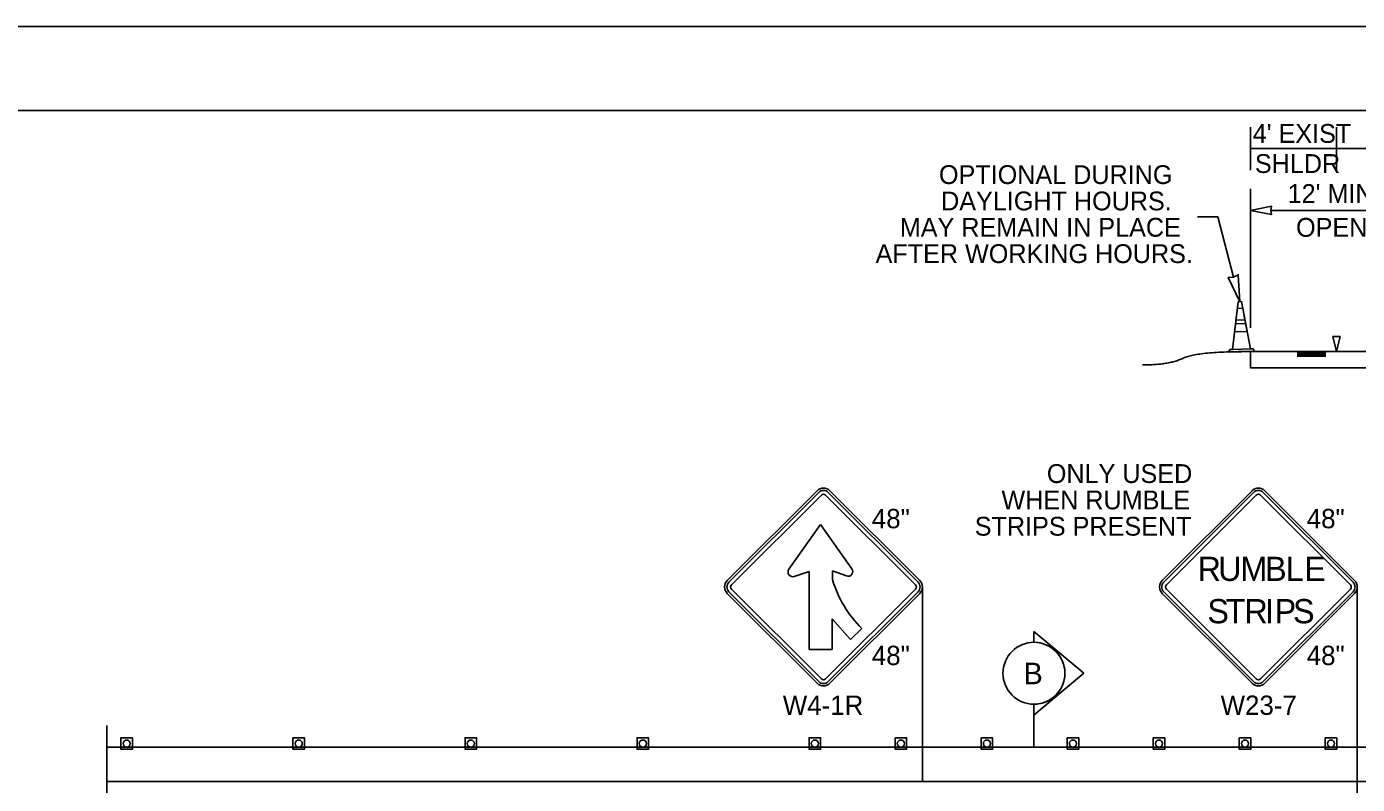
# Model space of a CAD drawing. Extents: x 99999 to 100116, y 99995 to 100013.
# Drawn here: x 100067.897 to 100072.847, y 100007.868 to 100010.687 of the extents above; entities that cross this region are included whole.
import ezdxf

# ---------------------------------------------------------------- set-up
doc = ezdxf.new("R2010")
doc.units = 0
for name, color, linetype in [('RD_MK_LineEdgeYellow', 7, 'Continuous'), ('SH_GI_PlotLimits', 7, 'Continuous'), ('SH_GI_SectionCut', 7, 'Continuous'), ('SH_GI_SheetBorder', 7, 'Continuous'), ('SH_TI_WZSectionCut', 7, 'Continuous'), ('TR_SN_ConstructionSigns', 7, 'Continuous'), ('TR_WZ_TrafficCone', 7, 'Continuous'), ('TR_WZ_TrafficConeElev', 7, 'Continuous'), ('TR_WZ_WorkZoneDetails', 7, 'Continuous'), ('TR_WZ_WorkZoneTextCurrent', 7, 'Continuous')]:
    doc.layers.add(name, color=color, linetype=linetype)

msp = doc.modelspace()

# ---------------------------------------------------------------- linework, layer by layer
at = {"layer": 'RD_MK_LineEdgeYellow'}
msp.add_line((100068.195, 100007.8789), (100075.43, 100007.8789), dxfattribs=at)
at = {"layer": 'SH_GI_PlotLimits'}
msp.add_lwpolyline([(100059.0625, 99999.6875), (100076.0625, 99999.6875), (100076.0625, 100010.6875), (100059.0625, 100010.6875)], close=True, dxfattribs=at)
at = {"layer": 'SH_GI_SectionCut'}
for p, q in [((100071.6444, 100008.397), (100071.6444, 100008.4377)), ((100071.6444, 100008.4377), (100071.8305, 100008.2818)), ((100071.8305, 100008.2818), (100071.6444, 100008.1259)), ((100071.6444, 100008.1259), (100071.6444, 100008.1666)), ((100071.6444, 100008.1259), (100071.6444, 100008.0069))]:
    msp.add_line(p, q, dxfattribs=at)
msp.add_circle((100071.6444, 100008.2818), 0.1152, dxfattribs=at)
msp.add_circle((100071.6444, 100008.2818), 0.1152, dxfattribs=at)
for start, end in [(90.0016, 269.9972), (269.9972, 90.0016), (269.9972, 90.0016)]:
    msp.add_arc((100071.6444, 100008.2818), 0.1152, start, end, dxfattribs=at)
at = {"layer": 'SH_GI_SheetBorder'}
msp.add_line((100060, 100010.375), (100075.75, 100010.375), dxfattribs=at)
at = {"layer": 'SH_TI_WZSectionCut'}
for p, q in [((100072.45, 100009.5666), (100072.45, 100010.0836)), ((100072.525, 100010.0036), (100073.335, 100010.0036))]:
    msp.add_line(p, q, dxfattribs=at)
msp.add_lwpolyline([(100072.45, 100010.0036), (100072.5286, 100009.9882), (100072.525, 100010.0036), (100072.5286, 100010.019)], close=True, dxfattribs=at)
at = {"layer": 'TR_SN_ConstructionSigns'}
for p, q in [((100070.8376, 100008.9607), (100070.5035, 100008.6266)), ((100070.8436, 100008.9548), (100070.5095, 100008.6207)), ((100071.2135, 100008.6207), (100070.8794, 100008.9548)), ((100071.2195, 100008.6266), (100070.8854, 100008.9607)), ((100072.4555, 100008.9607), (100072.1214, 100008.6266)), ((100072.4614, 100008.9548), (100072.1273, 100008.6207)), ((100072.8313, 100008.6207), (100072.4972, 100008.9548)), ((100072.8373, 100008.6266), (100072.5032, 100008.9607)), ((100070.5194, 100008.6107), (100070.8536, 100008.9448)), ((100070.8695, 100008.9448), (100071.2036, 100008.6107)), ((100072.1373, 100008.6107), (100072.4714, 100008.9448)), ((100072.4873, 100008.9448), (100072.8214, 100008.6107)), ((100070.7327, 100008.669), (100070.8506, 100008.8347)), ((100070.8506, 100008.8347), (100070.9671, 100008.6708)), ((100070.8079, 100008.6609), (100070.753, 100008.6419)), ((100070.8079, 100008.3708), (100070.8079, 100008.6609)), ((100070.9466, 100008.6438), (100070.8947, 100008.6624)), ((100070.8947, 100008.6624), (100070.8947, 100008.63)), ((100070.5035, 100008.5789), (100070.8376, 100008.2448)), ((100070.5095, 100008.5849), (100070.8436, 100008.2508)), ((100070.8536, 100008.2607), (100070.5194, 100008.5948)), ((100071.2036, 100008.5948), (100070.8695, 100008.2607)), ((100070.8794, 100008.2508), (100071.2135, 100008.5849)), ((100070.8854, 100008.2448), (100071.2195, 100008.5789)), ((100072.1214, 100008.5789), (100072.4555, 100008.2448)), ((100072.1273, 100008.5849), (100072.4614, 100008.2508)), ((100072.4714, 100008.2607), (100072.1373, 100008.5948)), ((100072.8214, 100008.5948), (100072.4873, 100008.2607)), ((100072.4972, 100008.2508), (100072.8313, 100008.5849)), ((100072.5032, 100008.2448), (100072.8373, 100008.5789)), ((100070.9624, 100008.4077), (100070.8932, 100008.4842)), ((100070.8932, 100008.4842), (100070.8932, 100008.3708)), ((100071.0036, 100008.4489), (100070.9624, 100008.4077)), ((100070.8932, 100008.3708), (100070.8079, 100008.3708))]:
    msp.add_line(p, q, dxfattribs=at)
for centre, radius, start, end in [((100070.8615, 100008.9369), 0.0338, 45, 135), ((100070.8615, 100008.9369), 0.0253, 45, 135), ((100070.8615, 100008.9369), 0.0113, 45, 135), ((100072.4793, 100008.9369), 0.0338, 45, 135), ((100072.4793, 100008.9369), 0.0253, 45, 135), ((100072.4793, 100008.9369), 0.0113, 45, 135), ((100070.7472, 100008.6587), 0.0177, 144.5862, 289.1062), ((100070.9526, 100008.6606), 0.0177, 250.3331, 35.4138), ((100070.5274, 100008.6028), 0.0338, 135, 225), ((100070.5274, 100008.6028), 0.0253, 135, 225), ((100070.5274, 100008.6028), 0.0113, 135, 225), ((100071.3078, 100008.7551), 0.4316, 196.843, 225.185), ((100071.1956, 100008.6028), 0.0113, 315, 45), ((100071.1956, 100008.6028), 0.0253, 315, 45), ((100071.1956, 100008.6028), 0.0338, 315, 45), ((100072.1452, 100008.6028), 0.0338, 135, 225), ((100072.1452, 100008.6028), 0.0253, 135, 225), ((100072.1452, 100008.6028), 0.0113, 135, 225), ((100072.8134, 100008.6028), 0.0113, 315, 45), ((100072.8134, 100008.6028), 0.0253, 315, 45), ((100072.8134, 100008.6028), 0.0338, 315, 45), ((100070.8615, 100008.2687), 0.0113, 225, 315), ((100072.4793, 100008.2687), 0.0113, 225, 315), ((100070.8615, 100008.2687), 0.0338, 225, 315), ((100070.8615, 100008.2687), 0.0253, 225, 315), ((100072.4793, 100008.2687), 0.0338, 225, 315), ((100072.4793, 100008.2687), 0.0253, 225, 315)]:
    msp.add_arc(centre, radius, start, end, dxfattribs=at)
at = {"layer": 'TR_WZ_TrafficCone'}
for points in [[(100068.2481, 100008.0416), (100068.2907, 100008.0416), (100068.2907, 100007.9989), (100068.2481, 100007.9989), (100068.2481, 100008.0416)], [(100068.2481, 100007.9989), (100068.2907, 100007.9989), (100068.2907, 100008.0416), (100068.2481, 100008.0416), (100068.2481, 100007.9989)], [(100068.8881, 100008.0416), (100068.9307, 100008.0416), (100068.9307, 100007.9989), (100068.8881, 100007.9989), (100068.8881, 100008.0416)], [(100068.8881, 100007.9989), (100068.9307, 100007.9989), (100068.9307, 100008.0416), (100068.8881, 100008.0416), (100068.8881, 100007.9989)], [(100069.5281, 100008.0416), (100069.5707, 100008.0416), (100069.5707, 100007.9989), (100069.5281, 100007.9989), (100069.5281, 100008.0416)], [(100069.5281, 100007.9989), (100069.5707, 100007.9989), (100069.5707, 100008.0416), (100069.5281, 100008.0416), (100069.5281, 100007.9989)], [(100070.1681, 100008.0416), (100070.2107, 100008.0416), (100070.2107, 100007.9989), (100070.1681, 100007.9989), (100070.1681, 100008.0416)], [(100070.1681, 100007.9989), (100070.2107, 100007.9989), (100070.2107, 100008.0416), (100070.1681, 100008.0416), (100070.1681, 100007.9989)], [(100070.8081, 100008.0416), (100070.8507, 100008.0416), (100070.8507, 100007.9989), (100070.8081, 100007.9989), (100070.8081, 100008.0416)], [(100070.8081, 100007.9989), (100070.8507, 100007.9989), (100070.8507, 100008.0416), (100070.8081, 100008.0416), (100070.8081, 100007.9989)], [(100071.1281, 100008.0416), (100071.1707, 100008.0416), (100071.1707, 100007.9989), (100071.1281, 100007.9989), (100071.1281, 100008.0416)], [(100071.1281, 100007.9989), (100071.1707, 100007.9989), (100071.1707, 100008.0416), (100071.1281, 100008.0416), (100071.1281, 100007.9989)], [(100071.4481, 100008.0416), (100071.4907, 100008.0416), (100071.4907, 100007.9989), (100071.4481, 100007.9989), (100071.4481, 100008.0416)], [(100071.4481, 100007.9989), (100071.4907, 100007.9989), (100071.4907, 100008.0416), (100071.4481, 100008.0416), (100071.4481, 100007.9989)], [(100071.7681, 100008.0416), (100071.8107, 100008.0416), (100071.8107, 100007.9989), (100071.7681, 100007.9989), (100071.7681, 100008.0416)], [(100071.7681, 100007.9989), (100071.8107, 100007.9989), (100071.8107, 100008.0416), (100071.7681, 100008.0416), (100071.7681, 100007.9989)], [(100072.0881, 100008.0416), (100072.1307, 100008.0416), (100072.1307, 100007.9989), (100072.0881, 100007.9989), (100072.0881, 100008.0416)], [(100072.0881, 100007.9989), (100072.1307, 100007.9989), (100072.1307, 100008.0416), (100072.0881, 100008.0416), (100072.0881, 100007.9989)], [(100072.4081, 100008.0416), (100072.4507, 100008.0416), (100072.4507, 100007.9989), (100072.4081, 100007.9989), (100072.4081, 100008.0416)], [(100072.4081, 100007.9989), (100072.4507, 100007.9989), (100072.4507, 100008.0416), (100072.4081, 100008.0416), (100072.4081, 100007.9989)], [(100072.7281, 100008.0416), (100072.7707, 100008.0416), (100072.7707, 100007.9989), (100072.7281, 100007.9989), (100072.7281, 100008.0416)], [(100072.7281, 100007.9989), (100072.7707, 100007.9989), (100072.7707, 100008.0416), (100072.7281, 100008.0416), (100072.7281, 100007.9989)]]:
    msp.add_lwpolyline(points, dxfattribs=at)
for centre in [(100068.2694, 100008.0202), (100068.9094, 100008.0202), (100069.5494, 100008.0202), (100070.1894, 100008.0202), (100070.8294, 100008.0202), (100071.1494, 100008.0202), (100071.4694, 100008.0202), (100071.7894, 100008.0202), (100072.1094, 100008.0202), (100072.4294, 100008.0202), (100072.7494, 100008.0202)]:
    msp.add_circle(centre, 0.0133, dxfattribs=at)
at = {"layer": 'TR_WZ_TrafficConeElev'}
for p, q in [((100072.3959, 100009.5953), (100072.4011, 100009.6388)), ((100072.4011, 100009.6388), (100072.4213, 100009.6395)), ((100072.4213, 100009.6395), (100072.4294, 100009.5964)), ((100072.4294, 100009.5964), (100072.3959, 100009.5953)), ((100072.3908, 100009.5518), (100072.3944, 100009.5819)), ((100072.4375, 100009.5534), (100072.3908, 100009.5518)), ((100072.3944, 100009.5819), (100072.4319, 100009.5832)), ((100072.4319, 100009.5832), (100072.4375, 100009.5534)), ((100072.3702, 100009.4827), (100072.3735, 100009.4861)), ((100072.3705, 100009.476), (100072.3702, 100009.4827)), ((100072.4629, 100009.4792), (100072.3705, 100009.476)), ((100072.4497, 100009.4887), (100072.4592, 100009.4891)), ((100072.4592, 100009.4891), (100072.4627, 100009.4858)), ((100072.4627, 100009.4858), (100072.4629, 100009.4792))]:
    msp.add_line(p, q, dxfattribs=at)
msp.add_lwpolyline([(100072.4497, 100009.4887), (100072.383, 100009.4865), (100072.4041, 100009.664), (100072.4166, 100009.6644)], close=True, dxfattribs=at)
msp.add_lwpolyline([(100072.4497, 100009.4887), (100072.383, 100009.4865), (100072.4041, 100009.664), (100072.4166, 100009.6644)], close=True, dxfattribs=at)
msp.add_lwpolyline([(100072.3735, 100009.4861), (100072.383, 100009.4865), (100072.4497, 100009.4887)], dxfattribs=at)
at = {"layer": 'TR_WZ_WorkZoneDetails'}
for p, q in [((100072.45, 100010.154), (100072.45, 100010.314)), ((100072.77, 100010.154), (100072.77, 100010.314)), ((100072.45, 100010.234), (100072.77, 100010.234)), ((100072.77, 100010.234), (100073.73, 100010.234)), ((100072.2522, 100009.9799), (100072.3284, 100009.9799)), ((100072.3868, 100009.7549), (100072.3284, 100009.9799)), ((100075.65, 100009.4787), (100072.45, 100009.4787)), ((100072.45, 100009.4787), (100072.45, 100009.4187)), ((100072.6236, 100009.4746), (100072.73, 100009.4746)), ((100072.6236, 100009.4701), (100072.73, 100009.4701)), ((100072.6236, 100009.4655), (100072.73, 100009.4655)), ((100072.6236, 100009.4614), (100072.73, 100009.4614)), ((100075.65, 100009.4187), (100072.45, 100009.4187)), ((100071.2294, 100007.8789), (100071.2294, 100008.6028)), ((100072.8472, 100007.559), (100072.8472, 100008.6028)), ((100068.195, 100008.0069), (100075.43, 100008.0069))]:
    msp.add_line(p, q, dxfattribs=at)
for points in [[(100072.4103, 100009.6642), (100072.367, 100009.7545), (100072.3868, 100009.7549), (100072.4044, 100009.7641)], [(100072.77, 100009.4787), (100072.7566, 100009.5346), (100072.7833, 100009.5346)]]:
    msp.add_lwpolyline(points, close=True, dxfattribs=at)
for points in [[(100072.7833, 100009.5346), (100072.7566, 100009.5346), (100072.77, 100009.4787), (100072.7833, 100009.5346)], [(100068.195, 100006.7109), (100068.195, 100007.433), (100068.131, 100007.433), (100068.259, 100007.5569), (100068.195, 100007.5569), (100068.195, 100008.0869)]]:
    msp.add_lwpolyline(points, dxfattribs=at)
msp.add_open_spline([(100072.45, 100009.4787), (100072.2491, 100009.4787), (100072.1487, 100009.429), (100072.0483, 100009.429)], degree=2, dxfattribs=at)

# ---------------------------------------------------------------- texts
at = {"layer": 'SH_GI_SectionCut'}
msp.add_text('B', height=0.08, rotation=0.0094, dxfattribs=at).set_placement((100071.6058, 100008.2411))
at = {"layer": 'TR_SN_ConstructionSigns'}
for s, height, p in [('48"', 0.072, (100071.0413, 100008.8213)), ('48"', 0.072, (100072.6591, 100008.8213)), ('R', 0.09, (100072.253, 100008.6253)), ('U', 0.09, (100072.3295, 100008.6253)), ('M', 0.09, (100072.4123, 100008.6253)), ('B', 0.09, (100072.5041, 100008.6253)), ('L', 0.09, (100072.5806, 100008.6253)), ('E', 0.09, (100072.6499, 100008.6253)), ('S', 0.09, (100072.2894, 100008.4678)), ('T', 0.09, (100072.3578, 100008.4678)), ('R', 0.09, (100072.4271, 100008.4678)), ('I', 0.09, (100072.5036, 100008.4678)), ('P', 0.09, (100072.5396, 100008.4678)), ('S', 0.09, (100072.608, 100008.4678)), ('48"', 0.072, (100071.0413, 100008.3122)), ('48"', 0.072, (100072.6591, 100008.3122)), ('W4-1R', 0.072, (100070.7101, 100008.1269)), ('W23-7', 0.072, (100072.3387, 100008.1269))]:
    msp.add_text(s, height=height, rotation=360, dxfattribs=at).set_placement(p)
at = {"layer": 'TR_WZ_WorkZoneDetails'}
for s, p in [("4' EXIST", (100072.4583, 100010.255)), ('SHLDR', (100072.4663, 100010.143)), ("12' MIN TEMP", (100072.5882, 100010.0316)), ('OPEN LANE', (100072.6194, 100009.9056)), ('ONLY USED', (100071.6923, 100008.9897)), ('WHEN RUMBLE', (100071.5235, 100008.8917)), ('STRIPS PRESENT', (100071.4242, 100008.7937))]:
    msp.add_text(s, height=0.07, dxfattribs=at).set_placement(p)
at = {"layer": 'TR_WZ_WorkZoneTextCurrent'}
for s, p in [('OPTIONAL DURING', (100071.291, 100010.1019)), ('DAYLIGHT HOURS.', (100071.2989, 100010.0039)), ('MAY REMAIN IN PLACE', (100071.1453, 100009.9059)), ('AFTER WORKING HOURS.', (100071.0552, 100009.8079))]:
    msp.add_text(s, height=0.07, dxfattribs=at).set_placement(p)

doc.saveas('drawing.dxf')
